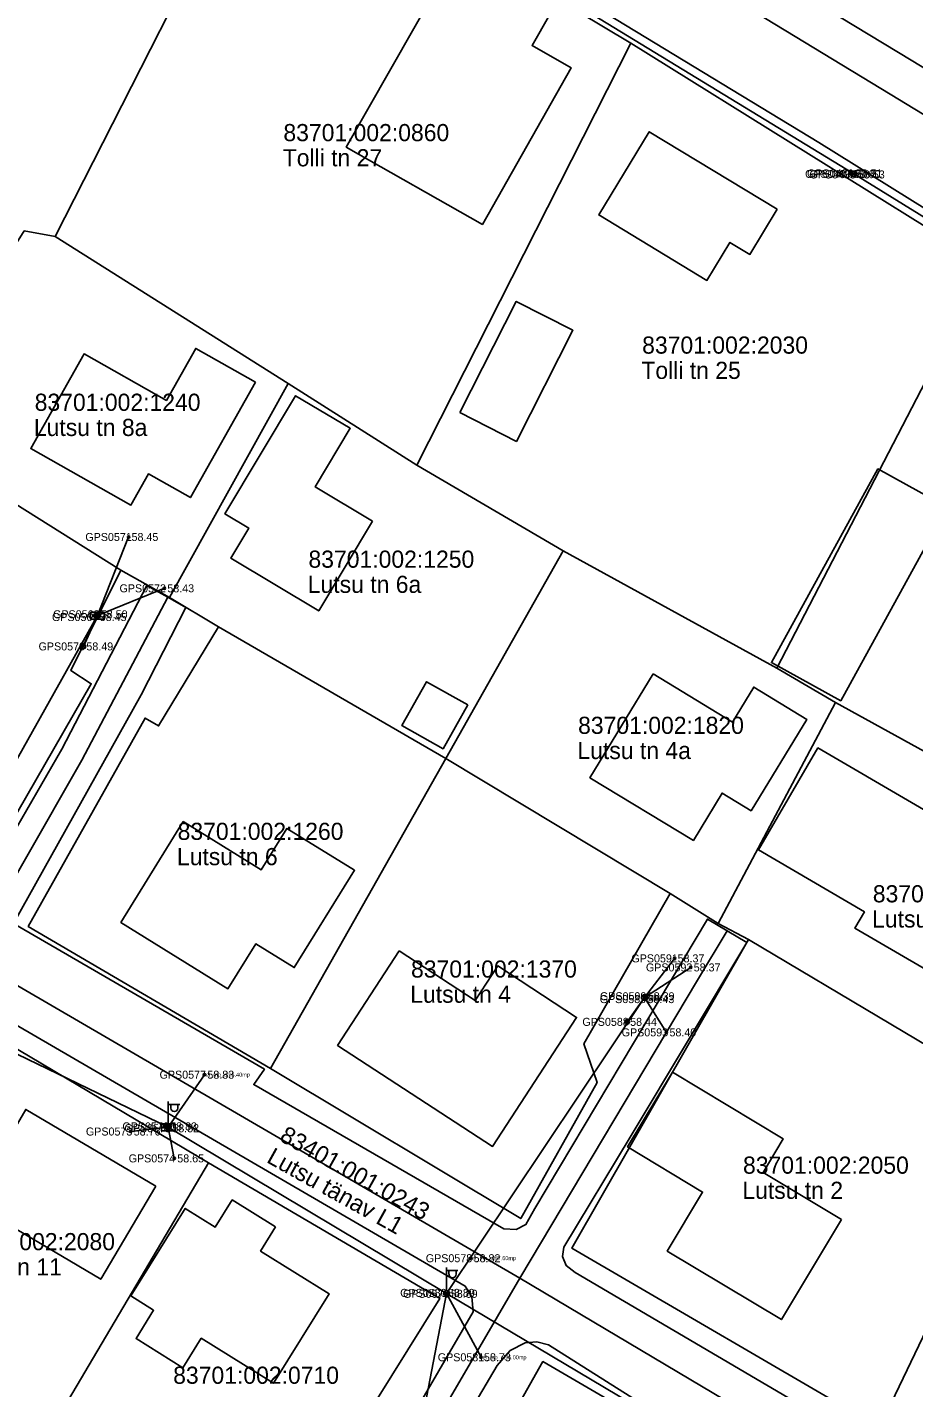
# Model space of a CAD drawing. Extents: x 580119 to 583377, y 6518915 to 6520820.
# Drawn here: x 582010.9 to 582088.4, y 6520218 to 6520337 of the extents above; entities that cross this region are included whole.
import ezdxf

# ---------------------------------------------------------------- set-up
doc = ezdxf.new("R2010")
doc.units = 0
for name, color, linetype in [('ELRAJATISMP', 7, 'Continuous'), ('Hoone Elu- või ühiskondlik hoone', 7, 'Continuous'), ('Hoone Kõrval- või tootmishoone', 7, 'Continuous'), ('L_AADRESS', 7, 'Continuous'), ('MAAMUDEL', 7, 'Continuous'), ('MOOTKORG-EH2000', 7, 'Continuous'), ('MOOTMPUNKT', 7, 'Continuous'), ('MOOTNR', 7, 'Continuous'), ('MPOHULIIN', 7, 'Continuous'), ('Muu rajatis Katusealune', 7, 'Continuous'), ('PIIR', 7, 'Continuous'), ('POST', 7, 'Continuous'), ('Rippe kõrgus', 7, 'Continuous'), ('Tee Liiklusala', 7, 'Continuous'), ('Tee Tänav Kruuskate', 7, 'Continuous'), ('Tee Tänav Püsikate', 7, 'Continuous'), ('TUNNUS', 7, 'Continuous')]:
    doc.layers.add(name, color=color, linetype=linetype)

msp = doc.modelspace()

# ---------------------------------------------------------------- linework, layer by layer
at = {"layer": 'ELRAJATISMP'}
for p, q in [((582016.89, 6520285.82), (582016.89, 6520285.22)), ((582017.17, 6520285.82), (582017.17, 6520285.22)), ((582023.1, 6520241.08), (582023.1, 6520240.48)), ((582023.37, 6520241.08), (582023.37, 6520240.48))]:
    msp.add_line(p, q, dxfattribs=at)
for points in [[(582016.43, 6520285.82), (582017.63, 6520285.82), (582017.63, 6520285.22), (582016.43, 6520285.22)], [(582022.63, 6520241.08), (582023.83, 6520241.08), (582023.83, 6520240.48), (582022.63, 6520240.48)]]:
    msp.add_lwpolyline(points, close=True, dxfattribs=at)
at = {"layer": 'Hoone Elu- või ühiskondlik hoone'}
for points in [[(582051.04, 6520341.24), (582056.59, 6520338.09), (582055.04, 6520335.37), (582058.46, 6520333.43), (582050.7, 6520319.73), (582038.79, 6520326.49), (582046.59, 6520340.22), (582049.52, 6520338.56)], [(582076.48, 6520321.07), (582074.09, 6520317.11), (582072.35, 6520318.16), (582070.33, 6520314.83), (582060.88, 6520320.56), (582065.29, 6520327.84)], [(582030.87, 6520305.94), (582025.17, 6520295.84), (582021.5, 6520297.91), (582019.96, 6520295.19), (582011.2, 6520300.13), (582015.87, 6520308.4), (582023.07, 6520304.34), (582025.64, 6520308.89)], [(582041.08, 6520293.79), (582036.39, 6520285.94), (582028.7, 6520290.55), (582030.27, 6520293.18), (582028.19, 6520294.42), (582034.37, 6520304.75), (582039.14, 6520301.9), (582036.09, 6520296.77)], [(582065.63, 6520280.42), (582072.56, 6520276.22), (582074.43, 6520279.27), (582079.06, 6520276.45), (582074.2, 6520268.46), (582071.66, 6520270), (582069.15, 6520265.86), (582060.11, 6520271.34)], [(582097.11, 6520264), (582091.07, 6520253.65), (582083.27, 6520258.19), (582084.11, 6520259.62), (582074.84, 6520265.03), (582080.04, 6520273.95)], [(582024.54, 6520267.51), (582031.35, 6520263.29), (582033.61, 6520266.92), (582039.53, 6520263.25), (582034.25, 6520254.74), (582030.88, 6520256.82), (582028.45, 6520252.9), (582019.09, 6520258.7)], [(582043.43, 6520256.21), (582050.07, 6520251.88), (582052.04, 6520254.89), (582058.94, 6520250.39), (582051.59, 6520239.11), (582038.03, 6520247.94)], [(582082.11, 6520232.72), (582076.85, 6520223.96), (582066.87, 6520229.96), (582069.96, 6520235.11), (582063.39, 6520239.06), (582067.31, 6520245.59), (582077.01, 6520239.77), (582075.26, 6520236.84)], [(582022.14, 6520235.63), (582017.33, 6520227.49), (582005.97, 6520234.21), (582006.31, 6520234.79), (582008.14, 6520237.89), (582010.77, 6520242.34)], [(582032.62, 6520232.07), (582031.31, 6520229.96), (582037.3, 6520226.23), (582032.43, 6520218.4), (582026.12, 6520222.33), (582024.51, 6520219.75), (582020.41, 6520222.3), (582021.95, 6520224.78), (582019.95, 6520226.03), (582024.71, 6520233.68), (582027.34, 6520232.05), (582028.83, 6520234.43)]]:
    msp.add_lwpolyline(points, close=True, dxfattribs=at)
at = {"layer": 'Hoone Kõrval- või tootmishoone'}
for points in [[(582048.73, 6520303.28), (582053.66, 6520313), (582058.61, 6520310.48), (582053.68, 6520300.76)], [(582091.35, 6520295.01), (582082.03, 6520278.08), (582075.97, 6520281.41), (582085.29, 6520298.35)]]:
    msp.add_lwpolyline(points, close=True, dxfattribs=at)
at = {"layer": 'MOOTMPUNKT'}
for centre in [(582082.91, 6520324.14), (582083.08, 6520324.19), (582083.28, 6520324.1), (582019.76, 6520292.4), (582022.89, 6520287.91), (582016.98, 6520285.4), (582017.07, 6520285.64), (582015.81, 6520282.83), (582067.51, 6520255.55), (582068.92, 6520254.76), (582064.88, 6520251.99), (582064.9, 6520252.24), (582063.36, 6520250), (582066.8, 6520249.08), (582026.39, 6520245.38), (582023.14, 6520240.86), (582023.32, 6520240.7), (582019.95, 6520240.41), (582023.76, 6520238.06), (582049.67, 6520229.33), (582047.43, 6520226.3), (582047.68, 6520226.22), (582050.58, 6520220.67)]:
    msp.add_circle(centre, 0.1, dxfattribs=at)
at = {"layer": 'MPOHULIIN'}
for p, q in [((582017.03, 6520285.52), (582019.76, 6520292.4)), ((582017.03, 6520285.52), (582022.89, 6520287.91)), ((581998.59, 6520252.67), (582017.03, 6520285.52)), ((582064.89, 6520252.12), (582068.92, 6520254.76)), ((582064.89, 6520252.12), (582066.8, 6520249.08)), ((582023.23, 6520240.78), (582026.39, 6520245.38)), ((582023.23, 6520240.78), (582019.95, 6520240.41)), ((582023.23, 6520240.78), (582023.76, 6520238.06)), ((582047.56, 6520226.26), (582050.58, 6520220.67))]:
    msp.add_line(p, q, dxfattribs=at)
for points in [[(582050.23, 6520344.28), (582083.18, 6520324.14), (582123.42, 6520299.31), (582167.33, 6520272.28), (582157.06, 6520224.19), (582147.76, 6520176.08), (582125.26, 6520179.6), (582101.28, 6520194.2)], [(582101.28, 6520194.2), (582072.88, 6520211.17), (582047.56, 6520226.26), (582064.89, 6520252.12), (582067.51, 6520255.55)], [(582047.56, 6520226.26), (582023.23, 6520240.78), (581998.59, 6520252.67)], [(582047.56, 6520226.26), (582041.9, 6520196.84), (582040.38, 6520195.81)]]:
    msp.add_lwpolyline(points, dxfattribs=at)
at = {"layer": 'Muu rajatis Katusealune'}
msp.add_lwpolyline([(582049.42, 6520277.72), (582047.27, 6520273.88), (582043.67, 6520275.9), (582045.82, 6520279.74)], close=True, dxfattribs=at)
at = {"layer": 'PIIR'}
for points in [[(582284.12, 6520257.02), (582261.11, 6520257.72), (582237.89, 6520257.97), (582223.55, 6520256.24), (582192.17, 6520260.67), (582164.12, 6520273.34), (582126.68, 6520296.88), (582094.75, 6520316.22), (582063.67, 6520335.59), (582031.69, 6520354.73), (581999.92, 6520374.14), (581993.27, 6520378.24), (581957.49, 6520399.79), (581930.32, 6520416.52), (581894, 6520438.54), (581862.44, 6520457.93)], [(582006.01, 6520261.34), (582016.49, 6520279.57), (582014.72, 6520280.72), (582019.09, 6520289.51), (582023.34, 6520287.11), (582027.62, 6520284.54), (582022.39, 6520275.88), (582021.21, 6520276.57), (582010.99, 6520258.34), (582032.18, 6520245.92), (582054.06, 6520232.79), (582060.73, 6520244.69), (582059.57, 6520248.09), (582067.13, 6520261.22), (582071.32, 6520258.6), (582073.96, 6520257.21), (582058.52, 6520230.22), (582085.43, 6520214.53)], [(582030.2, 6520198.89), (582046.99, 6520225.8), (582026.75, 6520237.66), (582006.96, 6520249.43)], [(582076.48, 6520208.35), (582056, 6520220.29), (582041.21, 6520194.04)]]:
    msp.add_lwpolyline(points, dxfattribs=at)
for points in [[(581999.92, 6520374.14), (582031.69, 6520354.73), (582013.33, 6520318.68), (582010.64, 6520319.17), (582007.43, 6520314.06), (581977.35, 6520329.37)], [(582031.69, 6520354.73), (582063.67, 6520335.59), (582044.98, 6520298.67), (582033.73, 6520305.82), (582013.33, 6520318.68)], [(582063.67, 6520335.59), (582094.75, 6520316.22), (582076.44, 6520280.94), (582057.75, 6520291.18), (582044.98, 6520298.67)], [(582007.43, 6520314.06), (582010.64, 6520319.17), (582013.33, 6520318.68), (582033.73, 6520305.82), (582023.34, 6520287.11), (582019.09, 6520289.51), (582000.23, 6520301.33)], [(582076.44, 6520280.94), (582094.75, 6520316.22), (582126.68, 6520296.88), (582109.22, 6520262.71), (582081.59, 6520277.92)], [(582023.34, 6520287.11), (582033.73, 6520305.82), (582044.98, 6520298.67), (582057.75, 6520291.18), (582047.51, 6520273.02), (582027.62, 6520284.54)], [(581996.95, 6520295.8), (582000.23, 6520301.33), (582019.09, 6520289.51), (582014.72, 6520280.72), (582016.49, 6520279.57), (582006.01, 6520261.34), (581984.07, 6520274.27)], [(582057.75, 6520291.18), (582076.44, 6520280.94), (582081.59, 6520277.92), (582071.32, 6520258.6), (582067.13, 6520261.22), (582047.51, 6520273.02)], [(582021.21, 6520276.57), (582022.39, 6520275.88), (582027.62, 6520284.54), (582047.51, 6520273.02), (582032.18, 6520245.92), (582010.99, 6520258.34)], [(582071.32, 6520258.6), (582081.59, 6520277.92), (582109.22, 6520262.71), (582108.08, 6520260.44), (582098.86, 6520242.4), (582073.96, 6520257.21)], [(582047.51, 6520273.02), (582067.13, 6520261.22), (582059.57, 6520248.09), (582060.73, 6520244.69), (582054.06, 6520232.79), (582032.18, 6520245.92)], [(582058.52, 6520230.22), (582073.96, 6520257.21), (582098.86, 6520242.4), (582097.81, 6520240.35), (582085.43, 6520214.53)], [(582006.96, 6520249.43), (582026.75, 6520237.66), (582010.72, 6520210.54), (581991.78, 6520221.9)], [(582085.43, 6520214.53), (582097.81, 6520240.35), (582116.98, 6520229.44), (582115.43, 6520226.17), (582104.08, 6520203.24)], [(582026.75, 6520237.66), (582046.99, 6520225.8), (582030.2, 6520198.89), (582010.72, 6520210.54)], [(582056, 6520220.29), (582076.48, 6520208.35), (582061.53, 6520181.85), (582058.56, 6520184.01), (582041.21, 6520194.04)]]:
    msp.add_lwpolyline(points, close=True, dxfattribs=at)
at = {"layer": 'POST'}
for p, q in [((582023.23, 6520241.03), (582023.23, 6520243.03)), ((582023.23, 6520242.78), (582024.23, 6520242.78)), ((582023.46, 6520242.46), (582023.46, 6520242.78)), ((582024.07, 6520242.46), (582024.07, 6520242.78)), ((582023.23, 6520240.78), (582023.23, 6520240.78)), ((582047.56, 6520226.51), (582047.56, 6520228.51)), ((582047.56, 6520228.26), (582048.56, 6520228.26)), ((582047.78, 6520227.93), (582047.78, 6520228.26)), ((582048.4, 6520227.93), (582048.4, 6520228.26)), ((582047.56, 6520226.26), (582047.56, 6520226.26))]:
    msp.add_line(p, q, dxfattribs=at)
for points in [[(582017.03, 6520285.52), (582015.81, 6520282.83)], [(582063.36, 6520250), (582064.89, 6520252.12)]]:
    msp.add_lwpolyline(points, dxfattribs=at)
for centre, radius in [((582083.18, 6520324.14), 0.25), ((582017.03, 6520285.52), 0.25), ((582015.81, 6520282.83), 0.2), ((582064.89, 6520252.12), 0.25), ((582063.36, 6520250), 0.2), ((582023.23, 6520240.78), 0.25), ((582047.56, 6520226.26), 0.25)]:
    msp.add_circle(centre, radius, dxfattribs=at)
for centre in [(582023.76, 6520242.46), (582048.09, 6520227.93)]:
    msp.add_arc(centre, 0.306, 180, 0, dxfattribs=at)
at = {"layer": 'Tee Liiklusala'}
for points in [[(581642.24, 6520605.03), (581666.59, 6520590.06), (581670.59, 6520587.55), (581796.41, 6520511.4), (581835.2, 6520487.74), (581935.02, 6520426.71), (581983.36, 6520397.53), (582007.48, 6520382.93), (582088.2, 6520334.1), (582141.71, 6520301.56), (582165.37, 6520287.35), (582174.12, 6520281.61), (582181.2, 6520277.68), (582186.15, 6520275.41), (582189.6, 6520274.06), (582195.31, 6520272.25), (582202.65, 6520270.15), (582210.44, 6520268.42), (582213.27, 6520268.02)], [(582164.21, 6520274.53), (582157.58, 6520278.25), (582127.39, 6520297.46), (582080.13, 6520326.9), (582043.05, 6520349.44)], [(582006.47, 6520260.97), (582013.92, 6520273.85), (582021.37, 6520288.17), (582023.19, 6520287.15), (582024.78, 6520286.24), (582020.85, 6520278.61), (582009.71, 6520258.61), (582031.64, 6520245.86), (582030.71, 6520244.51), (582052.57, 6520231.91), (582053.64, 6520231.85), (582054.51, 6520232.27), (582055.28, 6520233.68), (582070.38, 6520258.98), (582072.1, 6520257.95), (582073.81, 6520256.93), (582063.62, 6520239.93), (582057.83, 6520230.29), (582057.71, 6520229.49), (582058.02, 6520228.68), (582058.8, 6520228.08), (582079.9, 6520215.68)], [(582033.96, 6520197.24), (582049.88, 6520224.64), (582049.78, 6520225.96), (582049.2, 6520226.89), (582008.55, 6520250.53), (582006.49, 6520250.5), (582004.48, 6520249.64), (581998.41, 6520239.21), (581989.53, 6520223.21), (581987.68, 6520224.32), (581985.73, 6520225.53), (582001.41, 6520252.29), (582000.45, 6520254.57), (581954.17, 6520281.06), (581951.12, 6520281.6), (581948.5, 6520280.84), (581946.04, 6520279.06)], [(582071.14, 6520212.49), (582056.49, 6520221.77), (582055.46, 6520222.03), (582054.43, 6520221.93), (582053.14, 6520221.27), (582052, 6520219.95), (582037.68, 6520195.66)]]:
    msp.add_lwpolyline(points, dxfattribs=at)
at = {"layer": 'Tee Tänav Kruuskate'}
for points in [[(582005.78, 6520255.62), (582015.68, 6520272.89), (582023.19, 6520287.15)], [(582053.97, 6520227.58), (582069.52, 6520253.64), (582072.1, 6520257.95)], [(582035.8, 6520196.38), (582053.97, 6520227.58)]]:
    msp.add_lwpolyline(points, dxfattribs=at)
at = {"layer": 'Tee Tänav Püsikate'}
for points in [[(582000.38, 6520383.48), (582026.65, 6520367.48), (582056.26, 6520349.42), (582086.36, 6520331.13), (582121.31, 6520309.88), (582139.9, 6520298.57), (582163.58, 6520284.35), (582171.69, 6520279.52)], [(582005.78, 6520255.62), (582053.97, 6520227.58)], [(582053.97, 6520227.58), (582078.35, 6520213.11), (582100.43, 6520199.13)]]:
    msp.add_lwpolyline(points, dxfattribs=at)

# ---------------------------------------------------------------- texts
at = {"layer": 'L_AADRESS'}
for s, p in [('Tolli tn 27', (582033.24, 6520324.81)), ('Tolli tn 25', (582064.6, 6520306.22)), ('Lutsu tn 8a', (582011.48, 6520301.23)), ('Lutsu tn 6a', (582035.43, 6520287.51)), ('Lutsu tn 4a', (582059.01, 6520272.98)), ('Lutsu tn 6', (582023.99, 6520263.7)), ('Lutsu tn 2a', (582084.78, 6520258.25)), ('Lutsu tn 4', (582044.39, 6520251.67)), ('Lutsu tn 2', (582073.43, 6520234.52)), ('Lutsu tn 11', (582004, 6520227.82))]:
    msp.add_text(s, height=1.5, dxfattribs=at).set_placement(p)
msp.add_text('Lutsu tänav L1', height=1.5, rotation=330.8609, dxfattribs=at).set_placement((582031.74, 6520237.76))
at = {"layer": 'MAAMUDEL'}
for s, p in [(' mp_ohl', (582082.91, 6520323.97)), (' mp', (582082.91, 6520323.97)), (' kaabel', (582064.88, 6520251.81)), (' kaabel', (582064.9, 6520252.07))]:
    msp.add_text(s, height=0.35, dxfattribs=at).set_placement(p)
at = {"layer": 'MOOTKORG-EH2000'}
for s, p in [(' 58.60', (582082.91, 6520323.79)), (' 58.51', (582083.08, 6520323.84)), (' 58.53', (582083.28, 6520323.75)), (' 58.45', (582019.76, 6520292.05)), (' 58.43', (582022.89, 6520287.56)), (' 58.50', (582017.07, 6520285.29)), (' 58.45', (582016.98, 6520285.05)), (' 58.49', (582015.81, 6520282.48)), (' 58.37', (582067.51, 6520255.2)), (' 58.37', (582068.92, 6520254.41)), (' 58.39', (582064.9, 6520251.89)), (' 58.43', (582064.88, 6520251.64)), (' 58.44', (582063.36, 6520249.65)), (' 58.40', (582066.8, 6520248.73)), (' 58.83', (582026.39, 6520245.03)), (' 58.76', (582019.95, 6520240.06)), (' 58.83', (582023.14, 6520240.51)), (' 58.82', (582023.32, 6520240.35)), (' 58.65', (582023.76, 6520237.71)), (' 58.82', (582049.67, 6520228.98)), (' 58.89', (582047.43, 6520225.95)), (' 58.89', (582047.68, 6520225.87)), (' 58.73', (582050.58, 6520220.32))]:
    msp.add_text(s, height=0.7, dxfattribs=at).set_placement(p)
at = {"layer": 'MOOTNR'}
for s, p in [('GPS0487 ', (582078.92, 6520323.79)), ('GPS0486 ', (582079.09, 6520323.84)), ('GPS0485 ', (582079.3, 6520323.75)), ('GPS0571 ', (582015.98, 6520292.05)), ('GPS0572 ', (582018.97, 6520287.56)), ('GPS0568 ', (582013.16, 6520285.29)), ('GPS0569 ', (582013.06, 6520285.05)), ('GPS0570 ', (582011.89, 6520282.48)), ('GPS0591 ', (582063.73, 6520255.2)), ('GPS0592 ', (582065, 6520254.41)), ('GPS0590 ', (582060.98, 6520251.89)), ('GPS0589 ', (582060.96, 6520251.64)), ('GPS0588 ', (582059.44, 6520249.65)), ('GPS0593 ', (582062.88, 6520248.73)), ('GPS0577 ', (582022.47, 6520245.03)), ('GPS0573 ', (582016.03, 6520240.06)), ('GPS0576 ', (582019.22, 6520240.51)), ('GPS0575 ', (582019.4, 6520240.35)), ('GPS0574 ', (582019.77, 6520237.71)), ('GPS0578 ', (582045.75, 6520228.98)), ('GPS0580 ', (582043.51, 6520225.95)), ('GPS0579 ', (582043.76, 6520225.87)), ('GPS0581 ', (582046.8, 6520220.32))]:
    msp.add_text(s, height=0.7, dxfattribs=at).set_placement(p)
at = {"layer": 'Rippe kõrgus'}
for s, p in [(' el_mp_ohl5.40mp', (582026.39, 6520245.2)), (' el_mp_ohl7.60mp', (582049.67, 6520229.16)), (' el_mp_ohl6.00mp', (582050.58, 6520220.49))]:
    msp.add_text(s, height=0.35, dxfattribs=at).set_placement(p)
at = {"layer": 'TUNNUS'}
for s, p in [('83701:002:0860', (582033.3, 6520327.01)), ('83701:002:2030', (582064.67, 6520308.43)), ('83701:002:1240', (582011.55, 6520303.43)), ('83701:002:1250', (582035.49, 6520289.71)), ('83701:002:1820', (582059.07, 6520275.18)), ('83701:002:1260', (582024.05, 6520265.91)), ('83701:002:2060', (582084.84, 6520260.45)), ('83701:002:1370', (582044.46, 6520253.87)), ('83701:002:2050', (582073.49, 6520236.72)), ('83701:002:2080', (582004.07, 6520230.03)), ('83701:002:0710', (582023.66, 6520218.35))]:
    msp.add_text(s, height=1.5, dxfattribs=at).set_placement(p)
msp.add_text('83401:001:0243', height=1.5, rotation=330.8609, dxfattribs=at).set_placement((582032.87, 6520239.66))

doc.saveas('drawing.dxf')
